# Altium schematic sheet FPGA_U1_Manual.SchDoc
size C
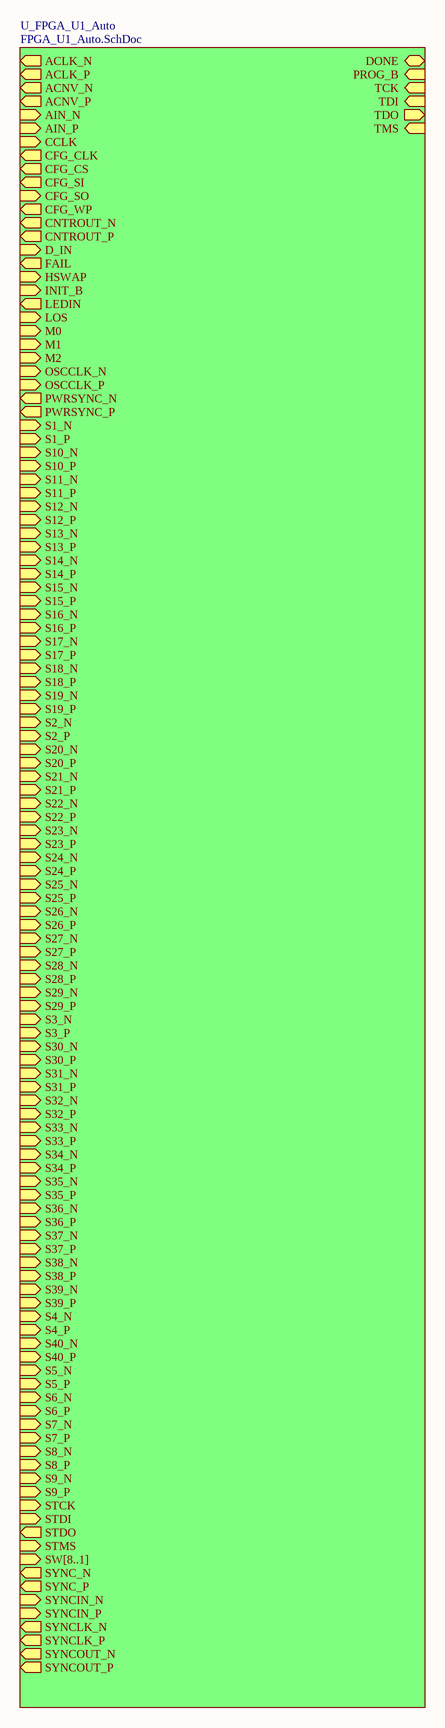
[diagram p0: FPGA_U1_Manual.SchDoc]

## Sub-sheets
U_FPGA_U1_Auto = FPGA_U1_Auto.SchDoc: ACLK_N (out), ACLK_P (out), ACNV_N (out), ACNV_P (out), AIN_N (in), AIN_P (in), CCLK (in), CFG_CLK (out), CFG_CS (out), CFG_SI (out), CFG_SO (in), CFG_WP (out), CNTROUT_N (out), CNTROUT_P (out), D_IN (in), FAIL (out), HSWAP (in), INIT_B (in), LEDIN (out), LOS (in), M0 (in), M1 (in), M2 (in), OSCCLK_N (in), OSCCLK_P (in), PWRSYNC_N (out), PWRSYNC_P (out), S1_N (in), S1_P (in), S10_N (in), S10_P (in), S11_N (in), S11_P (in), S12_N (in), S12_P (in), S13_N (in), S13_P (in), S14_N (in), S14_P (in), S15_N (in), S15_P (in), S16_N (in), S16_P (in), S17_N (in), S17_P (in), S18_N (in), S18_P (in), S19_N (in), S19_P (in), S2_N (in), S2_P (in), S20_N (in), S20_P (in), S21_N (in), S21_P (in), S22_N (in), S22_P (in), S23_N (in), S23_P (in), S24_N (in), S24_P (in), S25_N (in), S25_P (in), S26_N (in), S26_P (in), S27_N (in), S27_P (in), S28_N (in), S28_P (in), S29_N (in), S29_P (in), S3_N (in), S3_P (in), S30_N (in), S30_P (in), S31_N (in), S31_P (in), S32_N (in), S32_P (in), S33_N (in), S33_P (in), S34_N (in), S34_P (in), S35_N (in), S35_P (in), S36_N (in), S36_P (in), S37_N (in), S37_P (in), S38_N (in), S38_P (in), S39_N (in), S39_P (in), S4_N (in), S4_P (in), S40_N (in), S40_P (in), S5_N (in), S5_P (in), S6_N (in), S6_P (in), S7_N (in), S7_P (in), S8_N (in), S8_P (in), S9_N (in), S9_P (in), STCK (in), STDI (in), STDO (out), STMS (in), SW[8..1] (in), SYNC_N (out), SYNC_P (out), SYNCIN_N (in), SYNCIN_P (in), SYNCLK_N (out), SYNCLK_P (out), SYNCOUT_N (out), SYNCOUT_P (out), DONE (bidir), PROG_B (in), TCK (in), TDI (in), TDO (out), TMS (in)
